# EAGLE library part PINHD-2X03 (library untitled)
PIN HEADER
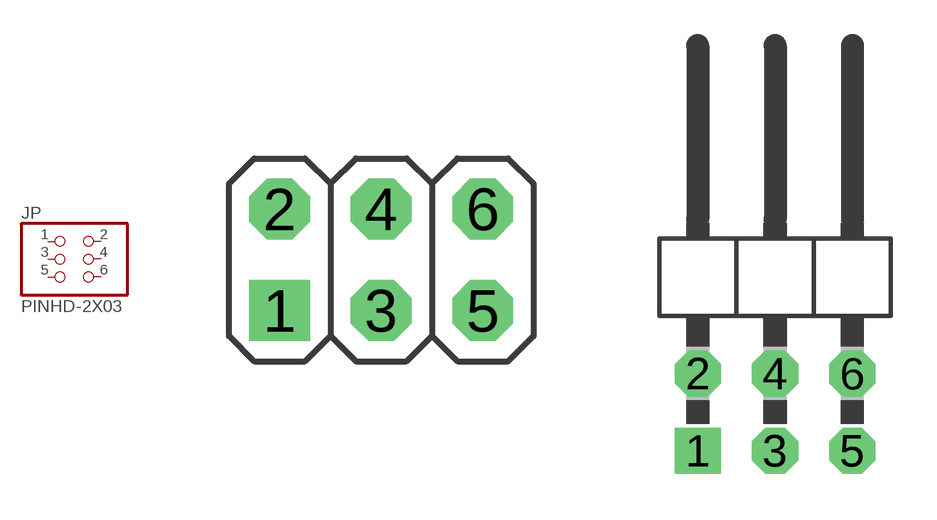
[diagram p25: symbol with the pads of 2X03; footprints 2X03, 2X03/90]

Designator prefix JP

## PINHD-2X03_2.54  [2X03]
1  1  pas
2  2  pas
3  3  pas
4  4  pas
5  5  pas
6  6  pas

## PINHD-2X03_2.54-90°  [2X03/90]
Pads as for 2X03

## PINHD-2X03_2.00  [2X03M]
Pads as for 2X03

## PINHD-2X03_2.54-SMD  [2X03SMD]
Pads as for 2X03

## PINHD-2X03_MICROMATCH  [MICROMATCH-6]
Pads as for 2X03

## PINHD-2X03_2.54-SMD-90°  [2X03SMD/90]
Pads as for 2X03

## Footprint 2X03 (pad centres in mm)
PIN HEADER - 2.54
drill 1.016 square: 1 -2.54,-1.27
drill 1.016 octagon: 2 -2.54,1.27; 3 0,-1.27; 4 0,1.27; 5 2.54,-1.27; 6 2.54,1.27

## Footprint 2X03/90 (pad centres in mm)
PIN HEADER - 2.54 90°
drill 1.016 square: 1 -2.54,-6.35
drill 1.016 octagon: 2 -2.54,-3.81; 3 0,-6.35; 4 0,-3.81; 5 2.54,-6.35; 6 2.54,-3.81

## Footprint 2X03M (pad centres in mm)
PIN HEADER - 2
drill 0.914 square: 1 -2,-1
drill 0.914 round: 2 -2,1; 3 0,-1; 4 0,1; 5 2,-1; 6 2,1

## Footprint 2X03SMD (pad centres in mm)
PIN HEADER - 2.54 SMD
smd 1.016 x 3.302: 1 -1.27,-3.81; 2 -1.27,1.27; 3 1.27,-3.81; 4 1.27,1.27; 5 3.81,-3.81; 6 3.81,1.27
